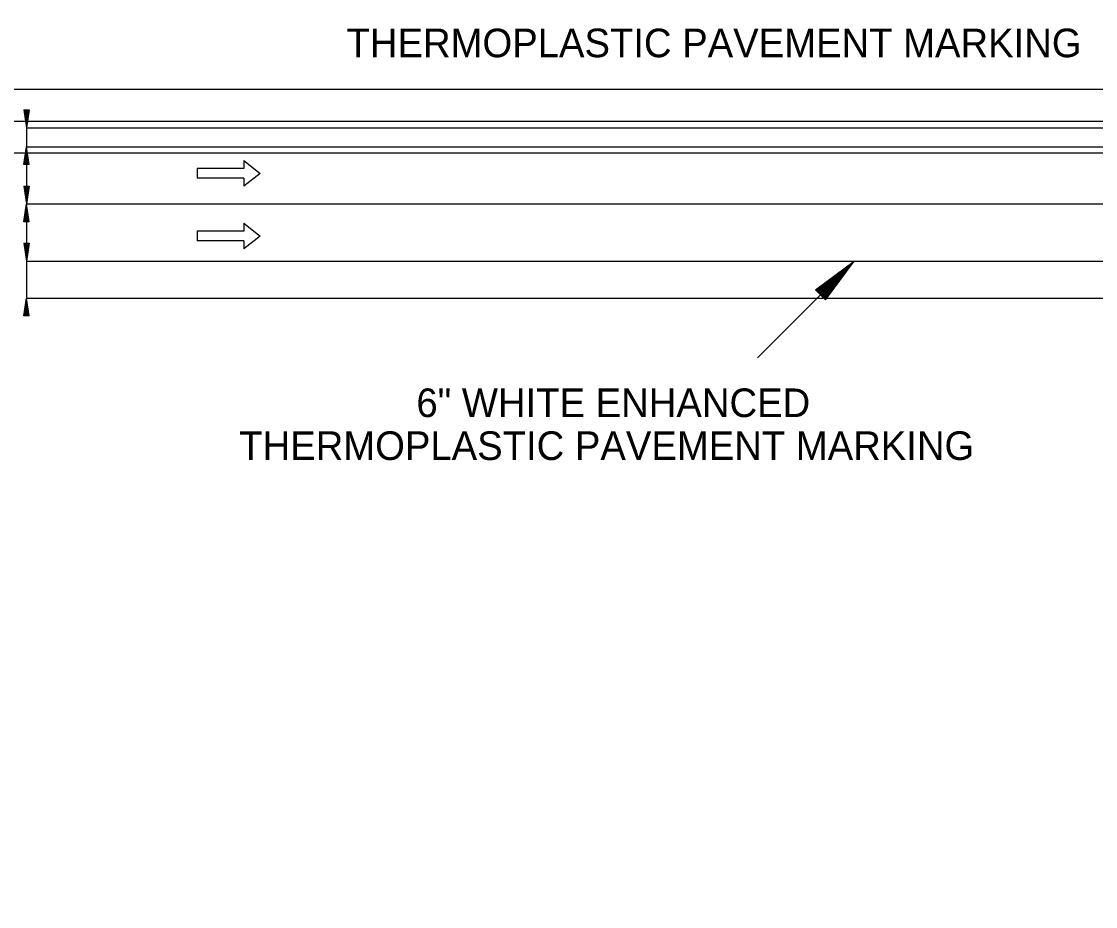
# Model space of a CAD drawing. Extents: x 1369905 to 1370238, y 380119 to 380332.
# Drawn here: x 1370023.8 to 1370091.4, y 380176.4 to 380232.1 of the extents above; entities that cross this region are included whole.
import ezdxf

# ---------------------------------------------------------------- set-up
doc = ezdxf.new("R2010")
doc.units = 0
for name, color, linetype in [('Default', 7, 'Continuous'), ('R_Border Plan-Plan', 7, 'Continuous'), ('R_Horz Alg', 7, 'Continuous'), ('R_MOT', 7, 'Continuous'), ('R_No Plot', 7, 'Continuous'), ('R_Proposed Road', 7, 'Continuous')]:
    doc.layers.add(name, color=color, linetype=linetype)

# ---------------------------------------------------------------- blocks, each defined once
blk = doc.blocks.new('SARROW')
at = {"layer": 'Default'}
for p, q in [((15.61, 8.23), (15.61, 3.23)), ((15.61, 8.23), (25.99, 0.23)), ((15.61, 3.23), (-13.81, 3.23)), ((-13.81, 3.23), (-13.81, -2.77)), ((25.99, 0.23), (15.61, -7.77)), ((15.61, -2.77), (-13.81, -2.77)), ((15.61, -2.77), (15.61, -7.77))]:
    blk.add_line(p, q, dxfattribs=at)

msp = doc.modelspace()

# ---------------------------------------------------------------- linework, layer by layer
at = {"layer": 'Default'}
for p, q in [((1370023.949, 380226.509), (1370024.117, 380225.384)), ((1370023.949, 380226.509), (1370024.286, 380226.509)), ((1370023.979, 380226.509), (1370024.117, 380225.572)), ((1370024.005, 380226.509), (1370024.117, 380225.766)), ((1370024.035, 380226.509), (1370024.117, 380225.954)), ((1370024.061, 380226.509), (1370024.117, 380226.146)), ((1370024.092, 380226.509), (1370024.117, 380226.333)), ((1370024.286, 380226.509), (1370024.117, 380225.384)), ((1370024.174, 380226.509), (1370024.117, 380226.146)), ((1370024.23, 380226.509), (1370024.117, 380225.766)), ((1370024.256, 380226.509), (1370024.117, 380225.572)), ((1370024.2, 380226.509), (1370024.117, 380225.954)), ((1370024.143, 380226.509), (1370024.117, 380226.333)), ((1370023.949, 380223.059), (1370024.117, 380224.184)), ((1370023.949, 380223.059), (1370024.117, 380224.184)), ((1370023.949, 380223.059), (1370024.117, 380224.184)), ((1370023.979, 380223.059), (1370024.117, 380223.996)), ((1370023.979, 380223.059), (1370024.117, 380223.996)), ((1370023.979, 380223.059), (1370024.117, 380223.996)), ((1370024.005, 380223.059), (1370024.117, 380223.801)), ((1370024.005, 380223.059), (1370024.117, 380223.801)), ((1370024.005, 380223.059), (1370024.117, 380223.801)), ((1370024.286, 380223.059), (1370024.117, 380224.184)), ((1370024.286, 380223.059), (1370024.117, 380224.184)), ((1370024.286, 380223.059), (1370024.117, 380224.184)), ((1370024.256, 380223.059), (1370024.117, 380223.996)), ((1370024.256, 380223.059), (1370024.117, 380223.996)), ((1370024.256, 380223.059), (1370024.117, 380223.996)), ((1370024.23, 380223.059), (1370024.117, 380223.801)), ((1370024.23, 380223.059), (1370024.117, 380223.801)), ((1370024.23, 380223.059), (1370024.117, 380223.801)), ((1370024.286, 380223.059), (1370023.949, 380223.059)), ((1370024.286, 380223.059), (1370023.949, 380223.059)), ((1370024.286, 380223.059), (1370023.949, 380223.059)), ((1370024.035, 380223.059), (1370024.117, 380223.614)), ((1370024.035, 380223.059), (1370024.117, 380223.614)), ((1370024.035, 380223.059), (1370024.117, 380223.614)), ((1370024.061, 380223.059), (1370024.117, 380223.422)), ((1370024.061, 380223.059), (1370024.117, 380223.422)), ((1370024.061, 380223.059), (1370024.117, 380223.422)), ((1370024.092, 380223.059), (1370024.117, 380223.234)), ((1370024.092, 380223.059), (1370024.117, 380223.234)), ((1370024.092, 380223.059), (1370024.117, 380223.234)), ((1370024.2, 380223.059), (1370024.117, 380223.614)), ((1370024.2, 380223.059), (1370024.117, 380223.614)), ((1370024.2, 380223.059), (1370024.117, 380223.614)), ((1370024.174, 380223.059), (1370024.117, 380223.422)), ((1370024.174, 380223.059), (1370024.117, 380223.422)), ((1370024.174, 380223.059), (1370024.117, 380223.422)), ((1370024.143, 380223.059), (1370024.117, 380223.234)), ((1370024.143, 380223.059), (1370024.117, 380223.234)), ((1370024.143, 380223.059), (1370024.117, 380223.234)), ((1370023.949, 380221.709), (1370024.117, 380220.584)), ((1370023.949, 380221.709), (1370024.286, 380221.709)), ((1370023.949, 380221.709), (1370024.117, 380220.584)), ((1370023.949, 380221.709), (1370024.286, 380221.709)), ((1370023.949, 380221.709), (1370024.117, 380220.584)), ((1370023.949, 380221.709), (1370024.286, 380221.709)), ((1370023.979, 380221.709), (1370024.117, 380220.772)), ((1370023.979, 380221.709), (1370024.117, 380220.772)), ((1370023.979, 380221.709), (1370024.117, 380220.772)), ((1370024.005, 380221.709), (1370024.117, 380220.966)), ((1370024.005, 380221.709), (1370024.117, 380220.966)), ((1370024.005, 380221.709), (1370024.117, 380220.966)), ((1370024.035, 380221.709), (1370024.117, 380221.154)), ((1370024.035, 380221.709), (1370024.117, 380221.154)), ((1370024.035, 380221.709), (1370024.117, 380221.154)), ((1370024.061, 380221.709), (1370024.117, 380221.346)), ((1370024.061, 380221.709), (1370024.117, 380221.346)), ((1370024.061, 380221.709), (1370024.117, 380221.346)), ((1370024.092, 380221.709), (1370024.117, 380221.533)), ((1370024.092, 380221.709), (1370024.117, 380221.533)), ((1370024.092, 380221.709), (1370024.117, 380221.533)), ((1370024.286, 380221.709), (1370024.117, 380220.584)), ((1370024.174, 380221.709), (1370024.117, 380221.346)), ((1370024.23, 380221.709), (1370024.117, 380220.966)), ((1370024.256, 380221.709), (1370024.117, 380220.772)), ((1370024.2, 380221.709), (1370024.117, 380221.154)), ((1370024.143, 380221.709), (1370024.117, 380221.533)), ((1370024.286, 380221.709), (1370024.117, 380220.584)), ((1370024.174, 380221.709), (1370024.117, 380221.346)), ((1370024.23, 380221.709), (1370024.117, 380220.966)), ((1370024.256, 380221.709), (1370024.117, 380220.772)), ((1370024.2, 380221.709), (1370024.117, 380221.154)), ((1370024.143, 380221.709), (1370024.117, 380221.533)), ((1370024.286, 380221.709), (1370024.117, 380220.584)), ((1370024.174, 380221.709), (1370024.117, 380221.346)), ((1370024.23, 380221.709), (1370024.117, 380220.966)), ((1370024.256, 380221.709), (1370024.117, 380220.772)), ((1370024.2, 380221.709), (1370024.117, 380221.154)), ((1370024.143, 380221.709), (1370024.117, 380221.533)), ((1370023.949, 380219.459), (1370024.117, 380220.584)), ((1370023.949, 380219.459), (1370024.117, 380220.584)), ((1370023.949, 380219.459), (1370024.117, 380220.584)), ((1370023.979, 380219.459), (1370024.117, 380220.396)), ((1370023.979, 380219.459), (1370024.117, 380220.396)), ((1370023.979, 380219.459), (1370024.117, 380220.396)), ((1370024.286, 380219.459), (1370024.117, 380220.584)), ((1370024.286, 380219.459), (1370024.117, 380220.584)), ((1370024.286, 380219.459), (1370024.117, 380220.584)), ((1370024.256, 380219.459), (1370024.117, 380220.396)), ((1370024.256, 380219.459), (1370024.117, 380220.396)), ((1370024.256, 380219.459), (1370024.117, 380220.396)), ((1370024.005, 380219.459), (1370024.117, 380220.201)), ((1370024.005, 380219.459), (1370024.117, 380220.201)), ((1370024.005, 380219.459), (1370024.117, 380220.201)), ((1370024.035, 380219.459), (1370024.117, 380220.014)), ((1370024.035, 380219.459), (1370024.117, 380220.014)), ((1370024.035, 380219.459), (1370024.117, 380220.014)), ((1370024.061, 380219.459), (1370024.117, 380219.822)), ((1370024.061, 380219.459), (1370024.117, 380219.822)), ((1370024.061, 380219.459), (1370024.117, 380219.822)), ((1370024.23, 380219.459), (1370024.117, 380220.201)), ((1370024.23, 380219.459), (1370024.117, 380220.201)), ((1370024.23, 380219.459), (1370024.117, 380220.201)), ((1370024.2, 380219.459), (1370024.117, 380220.014)), ((1370024.2, 380219.459), (1370024.117, 380220.014)), ((1370024.2, 380219.459), (1370024.117, 380220.014)), ((1370024.174, 380219.459), (1370024.117, 380219.822)), ((1370024.174, 380219.459), (1370024.117, 380219.822)), ((1370024.174, 380219.459), (1370024.117, 380219.822)), ((1370024.286, 380219.459), (1370023.949, 380219.459)), ((1370024.286, 380219.459), (1370023.949, 380219.459)), ((1370024.286, 380219.459), (1370023.949, 380219.459)), ((1370024.092, 380219.459), (1370024.117, 380219.634)), ((1370024.092, 380219.459), (1370024.117, 380219.634)), ((1370024.092, 380219.459), (1370024.117, 380219.634)), ((1370024.143, 380219.459), (1370024.117, 380219.634)), ((1370024.143, 380219.459), (1370024.117, 380219.634)), ((1370024.143, 380219.459), (1370024.117, 380219.634)), ((1370023.949, 380218.109), (1370024.117, 380216.984)), ((1370023.949, 380218.109), (1370024.286, 380218.109)), ((1370023.949, 380218.109), (1370024.117, 380216.984)), ((1370023.949, 380218.109), (1370024.286, 380218.109)), ((1370023.949, 380218.109), (1370024.117, 380216.984)), ((1370023.949, 380218.109), (1370024.286, 380218.109)), ((1370023.979, 380218.109), (1370024.117, 380217.172)), ((1370023.979, 380218.109), (1370024.117, 380217.172)), ((1370023.979, 380218.109), (1370024.117, 380217.172)), ((1370024.005, 380218.109), (1370024.117, 380217.366)), ((1370024.005, 380218.109), (1370024.117, 380217.366)), ((1370024.005, 380218.109), (1370024.117, 380217.366)), ((1370024.035, 380218.109), (1370024.117, 380217.554)), ((1370024.035, 380218.109), (1370024.117, 380217.554)), ((1370024.035, 380218.109), (1370024.117, 380217.554)), ((1370024.061, 380218.109), (1370024.117, 380217.746)), ((1370024.061, 380218.109), (1370024.117, 380217.746)), ((1370024.061, 380218.109), (1370024.117, 380217.746)), ((1370024.092, 380218.109), (1370024.117, 380217.933)), ((1370024.092, 380218.109), (1370024.117, 380217.933)), ((1370024.092, 380218.109), (1370024.117, 380217.933)), ((1370024.286, 380218.109), (1370024.117, 380216.984)), ((1370024.174, 380218.109), (1370024.117, 380217.746)), ((1370024.23, 380218.109), (1370024.117, 380217.366)), ((1370024.256, 380218.109), (1370024.117, 380217.172)), ((1370024.2, 380218.109), (1370024.117, 380217.554)), ((1370024.143, 380218.109), (1370024.117, 380217.933)), ((1370024.286, 380218.109), (1370024.117, 380216.984)), ((1370024.174, 380218.109), (1370024.117, 380217.746)), ((1370024.23, 380218.109), (1370024.117, 380217.366)), ((1370024.256, 380218.109), (1370024.117, 380217.172)), ((1370024.2, 380218.109), (1370024.117, 380217.554)), ((1370024.143, 380218.109), (1370024.117, 380217.933)), ((1370024.286, 380218.109), (1370024.117, 380216.984)), ((1370024.174, 380218.109), (1370024.117, 380217.746)), ((1370024.23, 380218.109), (1370024.117, 380217.366)), ((1370024.256, 380218.109), (1370024.117, 380217.172)), ((1370024.2, 380218.109), (1370024.117, 380217.554)), ((1370024.143, 380218.109), (1370024.117, 380217.933)), ((1370073.782, 380215.181), (1370076.222, 380216.984)), ((1370073.782, 380215.181), (1370076.222, 380216.984)), ((1370073.782, 380215.181), (1370076.222, 380216.984)), ((1370074.418, 380214.544), (1370076.222, 380216.984)), ((1370074.418, 380214.544), (1370076.222, 380216.984)), ((1370074.418, 380214.544), (1370076.222, 380216.984)), ((1370073.839, 380215.123), (1370075.867, 380216.63)), ((1370073.839, 380215.123), (1370075.867, 380216.63)), ((1370073.839, 380215.123), (1370075.867, 380216.63)), ((1370074.361, 380214.602), (1370075.867, 380216.63)), ((1370074.361, 380214.602), (1370075.867, 380216.63)), ((1370074.361, 380214.602), (1370075.867, 380216.63)), ((1370073.888, 380215.075), (1370075.5, 380216.263)), ((1370073.888, 380215.075), (1370075.5, 380216.263)), ((1370073.888, 380215.075), (1370075.5, 380216.263)), ((1370073.945, 380215.017), (1370075.146, 380215.908)), ((1370073.945, 380215.017), (1370075.146, 380215.908)), ((1370073.945, 380215.017), (1370075.146, 380215.908)), ((1370074.255, 380214.708), (1370075.146, 380215.908)), ((1370074.255, 380214.708), (1370075.146, 380215.908)), ((1370074.255, 380214.708), (1370075.146, 380215.908)), ((1370074.312, 380214.65), (1370075.5, 380216.263)), ((1370074.312, 380214.65), (1370075.5, 380216.263)), ((1370074.312, 380214.65), (1370075.5, 380216.263)), ((1370074.418, 380214.544), (1370073.782, 380215.181)), ((1370074.418, 380214.544), (1370073.782, 380215.181)), ((1370074.418, 380214.544), (1370073.782, 380215.181)), ((1370073.994, 380214.969), (1370074.785, 380215.548)), ((1370073.994, 380214.969), (1370074.785, 380215.548)), ((1370073.994, 380214.969), (1370074.785, 380215.548)), ((1370074.051, 380214.911), (1370074.431, 380215.193)), ((1370074.051, 380214.911), (1370074.431, 380215.193)), ((1370074.051, 380214.911), (1370074.431, 380215.193)), ((1370074.149, 380214.814), (1370074.431, 380215.193)), ((1370074.149, 380214.814), (1370074.431, 380215.193)), ((1370074.149, 380214.814), (1370074.431, 380215.193)), ((1370074.206, 380214.757), (1370074.785, 380215.548)), ((1370074.206, 380214.757), (1370074.785, 380215.548)), ((1370074.206, 380214.757), (1370074.785, 380215.548)), ((1370023.949, 380213.534), (1370024.117, 380214.659)), ((1370023.979, 380213.534), (1370024.117, 380214.471)), ((1370024.005, 380213.534), (1370024.117, 380214.276)), ((1370024.286, 380213.534), (1370024.117, 380214.659)), ((1370024.256, 380213.534), (1370024.117, 380214.471)), ((1370024.23, 380213.534), (1370024.117, 380214.276)), ((1370024.035, 380213.534), (1370024.117, 380214.089)), ((1370024.061, 380213.534), (1370024.117, 380213.897)), ((1370024.092, 380213.534), (1370024.117, 380213.709)), ((1370024.2, 380213.534), (1370024.117, 380214.089)), ((1370024.174, 380213.534), (1370024.117, 380213.897)), ((1370024.143, 380213.534), (1370024.117, 380213.709)), ((1370024.286, 380213.534), (1370023.949, 380213.534))]:
    msp.add_line(p, q, dxfattribs=at)
at = {"layer": 'R_Border Plan-Plan'}
msp.add_line((1369917.098, 380225.792), (1370233.278, 380225.792), dxfattribs=at)
at = {"layer": 'R_Horz Alg'}
msp.add_line((1370024.117, 380220.584), (1370129.117, 380220.584), dxfattribs=at)
at = {"layer": 'R_No Plot'}
for points in [[(1370231.278, 380227.792), (1369919.098, 380227.792), (1369919.098, 380326.522), (1370168.638, 380326.522), (1370168.638, 380316.642), (1370186.178, 380316.642), (1370210.278, 380316.642), (1370210.278, 380294.31), (1370231.278, 380294.31)], [(1369919.098, 380223.792), (1370231.278, 380223.792), (1370231.278, 380125.062), (1369919.098, 380125.062)]]:
    msp.add_lwpolyline(points, close=True, dxfattribs=at)
at = {"layer": 'R_Proposed Road'}
for p, q in [((1370024.117, 380225.384), (1370024.117, 380224.184)), ((1370024.117, 380225.384), (1370129.117, 380225.384)), ((1370024.117, 380224.184), (1370024.117, 380220.584)), ((1370024.117, 380224.184), (1370129.117, 380224.184)), ((1370024.117, 380224.184), (1370024.117, 380220.584)), ((1370024.117, 380224.184), (1370024.117, 380220.584)), ((1370024.117, 380220.584), (1370024.117, 380216.984)), ((1370024.117, 380220.584), (1370024.117, 380216.984)), ((1370024.117, 380220.584), (1370024.117, 380216.984)), ((1370024.117, 380216.984), (1370129.117, 380216.984)), ((1370024.117, 380216.984), (1370024.117, 380214.659)), ((1370070.138, 380210.901), (1370076.222, 380216.984)), ((1370070.138, 380210.901), (1370076.222, 380216.984)), ((1370070.138, 380210.901), (1370076.222, 380216.984)), ((1370024.117, 380214.659), (1370129.117, 380214.659))]:
    msp.add_line(p, q, dxfattribs=at)

# ---------------------------------------------------------------- block references
at = {"layer": 'R_MOT', "xscale": 0.1, "yscale": 0.10000000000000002, "rotation": 9.398539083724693e-12}
for p in [(1370036.236, 380222.487), (1370036.236, 380218.542)]:
    msp.add_blockref('SARROW', p, dxfattribs=at)

# ---------------------------------------------------------------- texts
at = {"layer": 'Default'}
for s, p in [('THERMOPLASTIC PAVEMENT MARKING', (1370044.266, 380229.818)), ('6" WHITE ENHANCED ', (1370048.664, 380207.168)), ('THERMOPLASTIC PAVEMENT MARKING', (1370037.51, 380204.468))]:
    msp.add_text(s, height=1.8, dxfattribs=at).set_placement(p)

doc.saveas('drawing.dxf')
